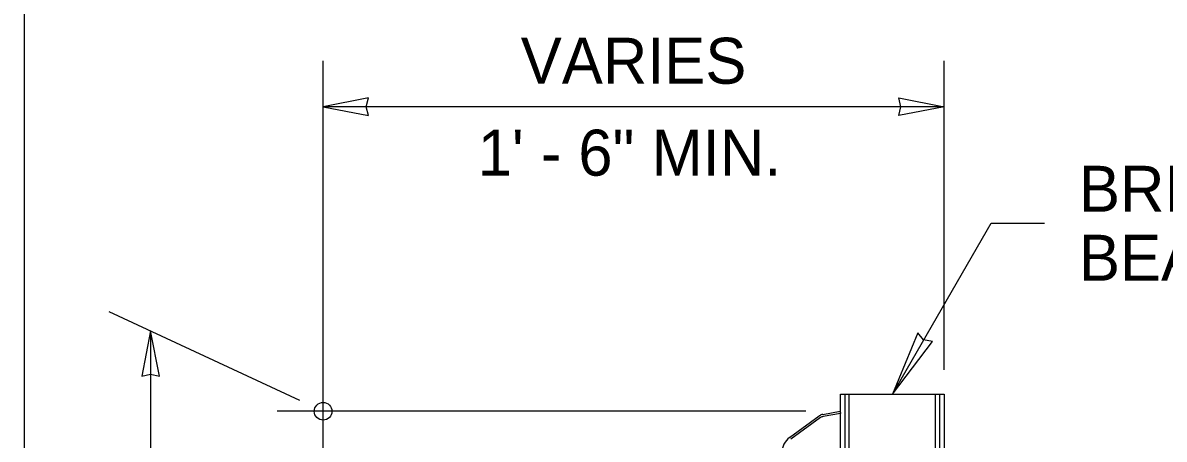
# Model space of a CAD drawing. Extents: x 36116 to 262144, y 33986 to 262144.
# Drawn here: x 100030.1 to 100427.1, y 100427.4 to 100572.2 of the extents above; entities that cross this region are included whole.
import ezdxf

# ---------------------------------------------------------------- set-up
doc = ezdxf.new("R2010")
doc.units = 0
for name, color, linetype in [('Level 15', 7, 'Continuous'), ('Level 20', 7, 'Continuous'), ('Level 22', 7, 'Continuous'), ('Level 4', 7, 'Continuous'), ('Level 5', 7, 'Continuous'), ('Level 9', 7, 'Continuous')]:
    doc.layers.add(name, color=color, linetype=linetype)

msp = doc.modelspace()

# ---------------------------------------------------------------- linework, layer by layer
at = {"layer": 'Level 15'}
for p, q in [((100134.51, 100253.31), (100134.51, 100559.05)), ((100350.51, 100451.45), (100350.51, 100559.05)), ((100350.51, 100543.05), (100134.51, 100543.05)), ((100332.51, 100443.05), (100366.83, 100502.49)), ((100366.83, 100502.49), (100385.44, 100502.49)), ((100060.01, 100471.79), (100126.28, 100440.89)), ((100074.51, 100465.03), (100074.51, 100255.03)), ((100302.38, 100437.05), (100118.51, 100437.05))]:
    msp.add_line(p, q, dxfattribs=at)
for points in [[(100134.51, 100543.05), (100150.24, 100539.97), (100149.51, 100543.05), (100150.24, 100546.13)], [(100350.51, 100543.05), (100334.79, 100539.97), (100335.51, 100543.05), (100334.79, 100546.13)], [(100074.51, 100465.03), (100071.43, 100449.3), (100074.51, 100450.03), (100077.6, 100449.3)], [(100332.51, 100443.05), (100346.51, 100461.33), (100343.4, 100461.91), (100341.34, 100464.31)]]:
    msp.add_lwpolyline(points, close=True, dxfattribs=at)
msp.add_circle((100134.51, 100437.05), 3.08, dxfattribs=at)
at = {"layer": 'Level 22'}
for p, q in [((100314.51, 100443.05), (100350.51, 100443.05)), ((100317.51, 100403.17), (100317.51, 100443.05)), ((100347.51, 100377.3), (100347.51, 100443.05))]:
    msp.add_line(p, q, dxfattribs=at)
for points in [[(100314.51, 100284.05), (100314.51, 100443.05)], [(100316.01, 100443.05), (100316.01, 100284.05)], [(100349.01, 100284.05), (100349.01, 100443.05)], [(100350.51, 100443.05), (100350.51, 100284.05)]]:
    msp.add_lwpolyline(points, dxfattribs=at)
at = {"layer": 'Level 4'}
msp.add_line((100030.51, 100617.36), (100030.51, 100239.05), dxfattribs=at)
at = {"layer": 'Level 5'}
msp.add_spline([(102147.43, 100634.59), (102161.82, 100639.44), (102158.74, 100645.43), (102162.73, 100648.51), (102160.91, 100653.23), (102160.91, 100653.23), (102154.44, 100663.63)], degree=3, dxfattribs=at)
at = {"layer": 'Level 9'}
for points in [[(100296.76, 100427.96), (100307.09, 100435.46)], [(100308.33, 100435.98), (100314.38, 100437.05), (100314.51, 100436.31), (100308.46, 100435.24)], [(100307.53, 100434.85), (100297.2, 100427.35)]]:
    msp.add_lwpolyline(points, dxfattribs=at)
for centre, radius, start, end in [((100308.85, 100433.03), 3, 100, 125.9834), ((100308.85, 100433.03), 2.25, 100, 125.9834), ((100300.51, 100422.8), 6.38, 125.9834, 235.3822)]:
    msp.add_arc(centre, radius, start, end, dxfattribs=at)

# ---------------------------------------------------------------- texts
at = {"layer": 'Level 20'}
for s, p in [('VARIES', (100203.26, 100551.05)), ('1\' - 6" MIN.', (100188.29, 100519.05)), ('BRIDGE RAIL THRIE', (100397.44, 100506.49)), ('BEAM RETROFIT', (100397.44, 100482.49))]:
    msp.add_text(s, height=16, dxfattribs=at).set_placement(p)

doc.saveas('drawing.dxf')
